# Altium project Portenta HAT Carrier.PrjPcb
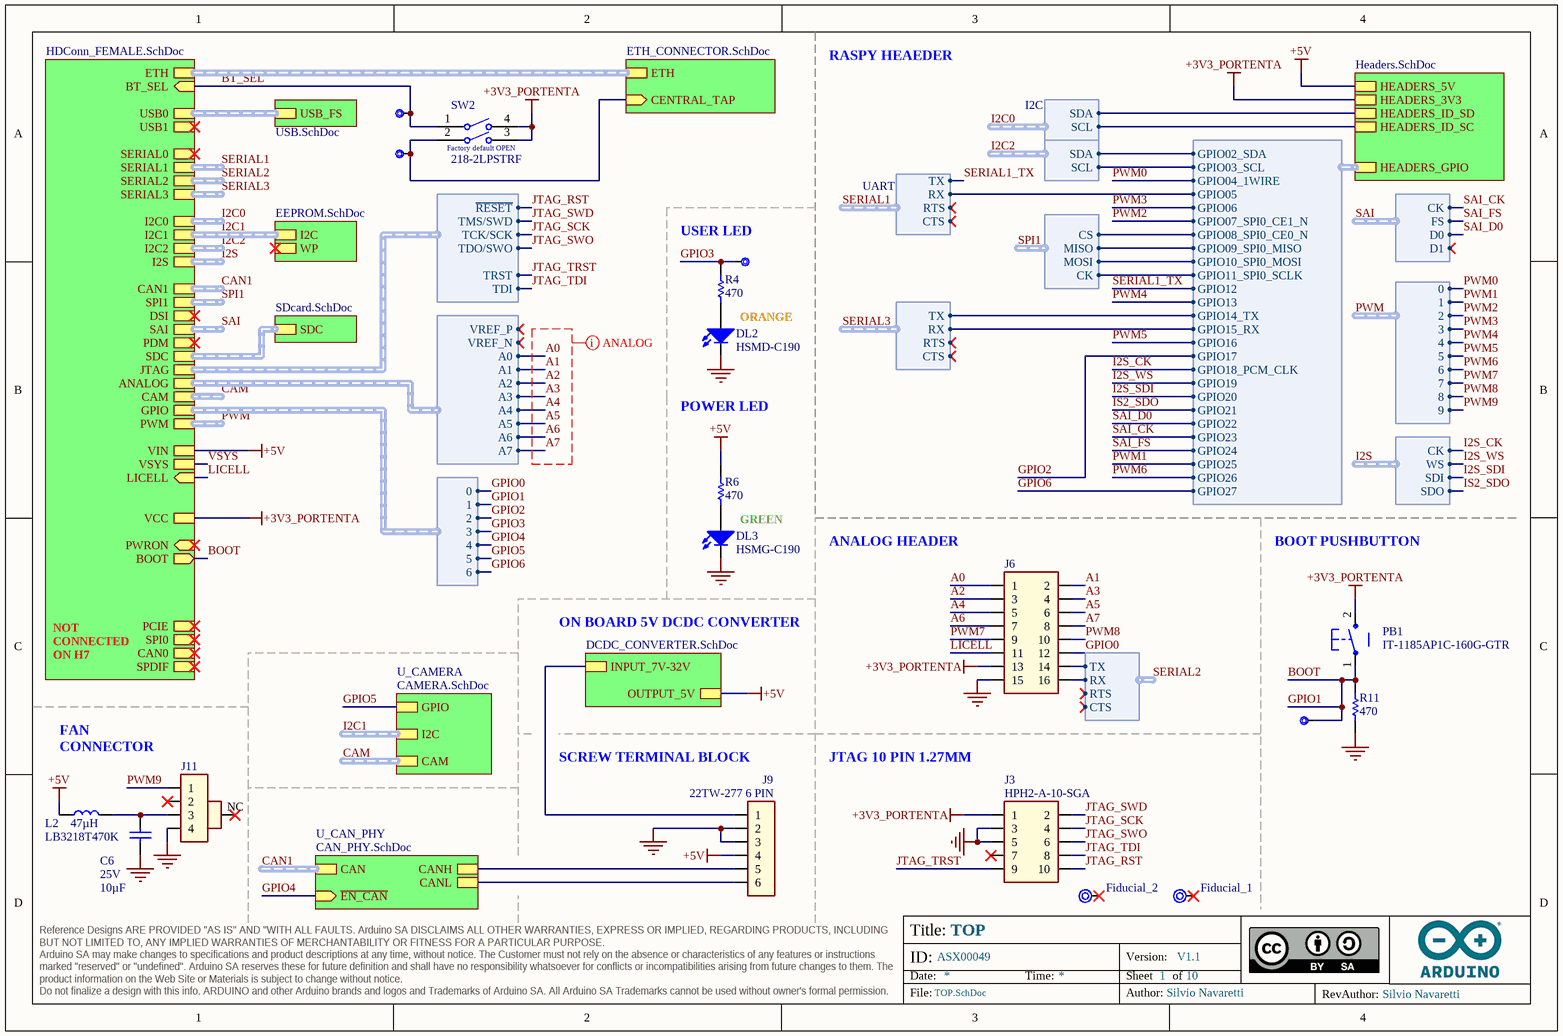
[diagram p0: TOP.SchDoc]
ASSEMBLY_BGA: _; ASSEMBLY_PRESSFIT: _; ASSEMBLY_SMD: X; ASSEMBLY_THT: X; BOARD_CODENAME: PORTENTA HAT CARRIER; BOARD_INFO_AUTHOR: Silvio Navaretti; BOARD_INFO_AUTHOR_REV: Silvio Navaretti; BOARD_INFO_Er: _; BOARD_INFO_FLEX: _; BOARD_INFO_FR4: X; BOARD_INFO_FR4_HTG: _; BOARD_INFO_IPC1: _; BOARD_INFO_IPC2: X; BOARD_INFO_IPC3: _; BOARD_INFO_IPC_NA: _; BOARD_INFO_NUMBER_OF_LAYERS: 4; BOARD_INFO_PCB_SIZE: 85mm x 56mm; BOARD_INFO_POLYMIDE: _; BOARD_INFO_RIGID: X; BOARD_INFO_RIGID/FLEX: _; BOARD_INFO_TBD: _; BOARD_INFO_THICKNESS: 1.6mm; DRILLS_BLIND: _; DRILLS_BURIED: _; DRILLS_COPPER_FILLING: _; DRILLS_FULL: X; DRILLS_LASER: _; DRILLS_PRESSFIT: _; DRILLS_RESIN_FILLING: _; DRILLS_SLOT: _; DRILLS_SOLDER_FILLING: X; FINISH_ADJUSTMENTS: _; FINISH_EDGE_PLATING: _; FINISH_ENIG: X; FINISH_HAL: _; FINISH_HAL_LF: _; FINISH_NI/AU: _; FINISH_SILK_BOTTOM: X; FINISH_SILK_COLOR: WHITE; FINISH_SILK_TOP: X; FINISH_SN/PB: _; FINISH_SOLDERMASK_BOTTOM: X; FINISH_SOLDERMASK_COLOR: BLACK; FINISH_SOLDERMASK_PEELABLE_BOTTOM: _; FINISH_SOLDERMASK_PEELABLE_COLOR: _; FINISH_SOLDERMASK_PEELABLE_TOP: _; FINISH_SOLDERMASK_TOP: X; FINISH_TABS: _; FINISH_TBD: _; INSULATION_MIN_INNER: 0.127mm; INSULATION_MIN_OUTER: 0.127mm; PANEL_MILLING: X; PANEL_NOT_REQUESTED: _; PANEL_NUMBER_OF_FIGURES: 6; PANEL_PROVIDED: X; PANEL_REQUESTED: _; PANEL_SCORING: X; PANEL_SIZE: 203mm x 188mm; PANEL_TABS: _; SKU: ASX00049; TRACK_MIN_WIDTH_INNER: 0.15mm; TRACK_MIN_WIDTH_OUTER: 0.15mm; VERSION: V1.1; VIA_1: _; VIA_1_HOLE_MM: _; VIA_1_PAD_MM: _; VIA_2: _; VIA_2_HOLE_MM: _; VIA_2_PAD_MM: _; VIA_3: _; VIA_3_HOLE_MM: _; VIA_3_PAD_MM: _; VIA_4: _; VIA_4_HOLE_MM: _; VIA_4_PAD_MM: _; VIA_5: _; VIA_5_HOLE_MM: _; VIA_5_PAD_MM: _; VIA_THROUGH: X; VIA_THROUGH_HOLE_MM: 0.3; VIA_THROUGH_PAD_MM: 0.6
10 sheets, 75 parts. Net scope: hierarchical (ports join the sheet entries above them; power ports are global).
Board files: PCB.PcbDoc, PANEL.PcbDoc
Sheets:
  TOP.SchDoc
    HDConnectors FEMALE = HDConn_FEMALE.SchDoc
    U_Headers = Headers.SchDoc
    MICRO USB CONNECTOR = USB.SchDoc
    U_SDcard = SDcard.SchDoc
    U_ETH_CONNECTOR = ETH_CONNECTOR.SchDoc
    DCDC_CONVERTER = DCDC_CONVERTER.SchDoc
    U_CAMERA = CAMERA.SchDoc
    U_CAN_PHY = CAN_PHY.SchDoc
    U_EEPROM = EEPROM.SchDoc

## Sheet TOP.SchDoc: TOP
size A4; Author: Silvio Navaretti; CompanyName: Arduino srl; DocumentNumber: ASX00049; Revision: V1.1; SheetNumber: 1; SheetTotal: 10; RevAuthor: Silvio Navaretti

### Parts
BOOT_PUSHBUTTON  CMP-018-0005-A.3  [TP-1.00MM]  (value not drawn)  (no BOM)
BT_SEL  CMP-018-0005-A.3  [TP-1.00MM]  (value not drawn)  (no BOM)
C6  value 10µF  Voltage: 25V  [CAP-0603]  (hidden comment: C1608A106M250NT)
CENTER_TAP  CMP-018-0005-A.3  [TP-1.00MM]  (value not drawn)  (no BOM)
DL2  HSMD-C190  [LEDC1608X80N-AK]
DL3  HSMG-C190  [LEDC1608X80N-AK]
Fiducial_1  Fiducial mark 1mm with 2mm solder  [Fiducial mark 1mm with circle-Footprint-1]  (value not drawn)  (no BOM)
Fiducial_2  Fiducial mark 1mm with 2mm solder  [Fiducial mark 1mm with circle-Footprint-1]  (value not drawn)  (no BOM)
J3  HPH2-A-10-SGA  [PINHEAD_2X05_127]
J6  PH2-16-UA  [PIN HEADER 2.54mm VERT. 2x8POS]  (value not drawn)
J9  22TW-277 6 PIN  [22TW-277 6 PIN]
J11  47053-1000  [47053-1000-Footprint-1]  (value not drawn)
L2  LB3218T470K  Inductance: 47µH  [INDC3218X20N]
LED_USER  CMP-018-0005-A.3  [TP-1.00MM]  (value not drawn)  (no BOM)
PB1  IT-1185AP1C-160G-GTR  [C&K_PTS820_NO_HOLES-1]
R4  value 470  [RES-0603]  (hidden comment: CRCW0603470RFKEAC)
R6  value 470  [RES-0603]  (hidden comment: CRCW0603470RFKEAC)
R11  value 470  [RES-0603]  (hidden comment: CRCW0603470RFKEAC)
SW2  218-2LPSTRF  [CTS-218-2LPST_V]

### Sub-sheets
DCDC_CONVERTER = DCDC_CONVERTER.SchDoc: INPUT_7V-32V, OUTPUT_5V
HDConnectors FEMALE = HDConn_FEMALE.SchDoc: PWRON (in), BOOT (out), USB1 (harness USB), SERIAL0 (harness UART), SAI (harness SAI), I2C2 (harness I2C), USB0 (harness USB), JTAG (harness JTAG), BT_SEL (in), I2S (harness I2S), I2C0 (harness I2C), ETH (harness ETH), PWM (harness GPIO), I2C1 (harness I2C), GPIO (harness GPIO), SPI1 (harness SPI), VCC, SERIAL3 (harness UART), CAM (harness CAMERA), LICELL (in), PDM (harness PDM), DSI (harness DISPLAY), CAN1 (harness CAN), SDC (harness SDC), SERIAL2 (harness UART), ANALOG (harness ANALOG), SERIAL1 (harness UART), VIN, VSYS, CAN0 (harness GPIO), SPI0 (harness GPIO), PCIE (harness GPIO), SPDIF (harness GPIO)
MICRO USB CONNECTOR = USB.SchDoc: USB_FS (harness USB)
U_CAMERA = CAMERA.SchDoc: I2C (harness I2C), CAM (harness CAMERA), GPIO
U_CAN_PHY = CAN_PHY.SchDoc: CAN (harness CAN), ~{EN_CAN} (in), CANH, CANL
U_EEPROM = EEPROM.SchDoc: I2C (harness I2C), WP
U_ETH_CONNECTOR = ETH_CONNECTOR.SchDoc: ETH (harness ETH), CENTRAL_TAP (in)
U_Headers = Headers.SchDoc: HEADERS_ID_SD, HEADERS_ID_SC, HEADERS_GPIO (harness HEADERS_GPIO), HEADERS_3V3, HEADERS_5V
U_SDcard = SDcard.SchDoc: SDC (harness SDC)

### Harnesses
HEADERS_GPIO: GPIO02_SDA, GPIO03_SCL, GPIO04_1WIRE, GPIO05, GPIO06, GPIO07_SPI0_CE1_N, GPIO08_SPI0_CE0_N, GPIO09_SPI0_MISO, GPIO10_SPI0_MOSI, GPIO11_SPI0_SCLK, GPIO12, GPIO13, GPIO14_TX, GPIO15_RX, GPIO16, GPIO17, GPIO18_PCM_CLK, GPIO19, GPIO20, GPIO21, GPIO22, GPIO23, GPIO24, GPIO25, GPIO26, GPIO27
UART: RX, TX, RTS, CTS
I2S: CK, SDI, SDO, WS
SPI: CS, CK, MISO, MOSI
I2C: SCL, SDA
I2C: SDA, SCL
SAI: CK, FS, D0, D1
JTAG: ~{RESET}, TCK/SCK, TDI, TDO/SWO, TMS/SWD, TRST
GPIO: 0, 1, 2, 3, 4, 5, 6
ANALOG: VREF_P, A0, A1, A2, A3, A7, A6, A5, A4, VREF_N
PWM: 0, 1, 2, 3, 4, 5, 6, 7, 8, 9

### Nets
+3V3_PORTENTA: J3.1 J6.13 PB1.2 SW2.3 SW2.4 ; sheet HDConnectors FEMALE/VCC, sheet U_Headers/HEADERS_3V3
+5V: J9.4 L2.1 R6.2 ; sheet HDConnectors FEMALE/VIN, sheet U_Headers/HEADERS_5V, sheet DCDC_CONVERTER/OUTPUT_5V
GND: C6.1 DL2.C DL3.C J3.3 J3.5 J6.15 J9.2 J9.3 J11.4 R11.1
A0: J6.1 ; sheet HDConnectors FEMALE/ANALOG.A0
A1: J6.2 ; sheet HDConnectors FEMALE/ANALOG.A1
A2: J6.3 ; sheet HDConnectors FEMALE/ANALOG.A2
A3: J6.4 ; sheet HDConnectors FEMALE/ANALOG.A3
A4: J6.5 ; sheet HDConnectors FEMALE/ANALOG.A4
A5: J6.6 ; sheet HDConnectors FEMALE/ANALOG.A5
A6: J6.7 ; sheet HDConnectors FEMALE/ANALOG.A6
A7: J6.8 ; sheet HDConnectors FEMALE/ANALOG.A7
BOOT: BOOT_PUSHBUTTON.X PB1.1 R11.2 ; sheet HDConnectors FEMALE/BOOT, sheet HDConnectors FEMALE/GPIO.1  [also labelled GPIO1]
BT_SEL: BT_SEL.X SW2.1 ; sheet HDConnectors FEMALE/BT_SEL
GPIO0: J6.12 ; sheet HDConnectors FEMALE/GPIO.0
GPIO2: sheet U_Headers/HEADERS_GPIO.GPIO17, sheet HDConnectors FEMALE/GPIO.2  [project net GPIO17]
GPIO02_SDA: sheet U_Headers/HEADERS_GPIO.GPIO02_SDA, sheet HDConnectors FEMALE/I2C2.SDA
GPIO3: LED_USER.X R4.2 ; sheet HDConnectors FEMALE/GPIO.3
GPIO03_SCL: sheet U_Headers/HEADERS_GPIO.GPIO03_SCL, sheet HDConnectors FEMALE/I2C2.SCL
GPIO4: sheet U_CAN_PHY/~{EN_CAN}, sheet HDConnectors FEMALE/GPIO.4
GPIO05: sheet U_Headers/HEADERS_GPIO.GPIO05, sheet HDConnectors FEMALE/SERIAL1.RX
GPIO5: sheet U_CAMERA/GPIO, sheet HDConnectors FEMALE/GPIO.5
GPIO6: sheet U_Headers/HEADERS_GPIO.GPIO27, sheet HDConnectors FEMALE/GPIO.6  [project net GPIO27]
GPIO08_SPI0_CE0_N: sheet U_Headers/HEADERS_GPIO.GPIO08_SPI0_CE0_N, sheet HDConnectors FEMALE/SPI1.CS
GPIO09_SPI0_MISO: sheet U_Headers/HEADERS_GPIO.GPIO09_SPI0_MISO, sheet HDConnectors FEMALE/SPI1.MISO
GPIO10_SPI0_MOSI: sheet U_Headers/HEADERS_GPIO.GPIO10_SPI0_MOSI, sheet HDConnectors FEMALE/SPI1.MOSI
GPIO11_SPI0_SCLK: sheet U_Headers/HEADERS_GPIO.GPIO11_SPI0_SCLK, sheet HDConnectors FEMALE/SPI1.CK
GPIO14_TX: sheet U_Headers/HEADERS_GPIO.GPIO14_TX, sheet HDConnectors FEMALE/SERIAL3.TX
GPIO15_RX: sheet U_Headers/HEADERS_GPIO.GPIO15_RX, sheet HDConnectors FEMALE/SERIAL3.RX
I2C0.SCL: sheet U_Headers/HEADERS_ID_SC, sheet HDConnectors FEMALE/I2C0.SCL
I2C0.SDA: sheet U_Headers/HEADERS_ID_SD, sheet HDConnectors FEMALE/I2C0.SDA
I2S_CK: sheet U_Headers/HEADERS_GPIO.GPIO18_PCM_CLK, sheet HDConnectors FEMALE/I2S.CK  [project net GPIO18_PCM_CLK]
I2S_SDI: sheet U_Headers/HEADERS_GPIO.GPIO20, sheet HDConnectors FEMALE/I2S.SDI  [project net GPIO20]
I2S_WS: sheet U_Headers/HEADERS_GPIO.GPIO19, sheet HDConnectors FEMALE/I2S.WS  [project net GPIO19]
IS2_SDO: sheet U_Headers/HEADERS_GPIO.GPIO21, sheet HDConnectors FEMALE/I2S.SDO  [project net GPIO21]
JTAG_RST: J3.10 ; sheet HDConnectors FEMALE/JTAG.~{RESET}
JTAG_SCK: J3.4 ; sheet HDConnectors FEMALE/JTAG.TCK/SCK
JTAG_SWD: J3.2 ; sheet HDConnectors FEMALE/JTAG.TMS/SWD
JTAG_SWO: J3.6 ; sheet HDConnectors FEMALE/JTAG.TDO/SWO
JTAG_TDI: J3.8 ; sheet HDConnectors FEMALE/JTAG.TDI
JTAG_TRST: J3.9 ; sheet HDConnectors FEMALE/JTAG.TRST
LICELL: J6.11 ; sheet HDConnectors FEMALE/LICELL
PWM0: sheet U_Headers/HEADERS_GPIO.GPIO04_1WIRE, sheet HDConnectors FEMALE/PWM.0  [project net GPIO04_1WIRE]
PWM1: sheet U_Headers/HEADERS_GPIO.GPIO25, sheet HDConnectors FEMALE/PWM.1  [project net GPIO25]
PWM2: sheet U_Headers/HEADERS_GPIO.GPIO07_SPI0_CE1_N, sheet HDConnectors FEMALE/PWM.2  [project net GPIO07_SPI0_CE1_N]
PWM3: sheet U_Headers/HEADERS_GPIO.GPIO06, sheet HDConnectors FEMALE/PWM.3  [project net GPIO06]
PWM4: sheet U_Headers/HEADERS_GPIO.GPIO13, sheet HDConnectors FEMALE/PWM.4  [project net GPIO13]
PWM5: sheet U_Headers/HEADERS_GPIO.GPIO16, sheet HDConnectors FEMALE/PWM.5  [project net GPIO16]
PWM6: sheet U_Headers/HEADERS_GPIO.GPIO26, sheet HDConnectors FEMALE/PWM.6  [project net GPIO26]
PWM7: J6.9 ; sheet HDConnectors FEMALE/PWM.7  [project net PWM.7]
PWM8: J6.10 ; sheet HDConnectors FEMALE/PWM.8  [project net PWM.8]
PWM9: J11.1 ; sheet HDConnectors FEMALE/PWM.9  [project net PWM.9]
SAI_CK: sheet U_Headers/HEADERS_GPIO.GPIO23, sheet HDConnectors FEMALE/SAI.CK  [project net GPIO23]
SAI_D0: sheet U_Headers/HEADERS_GPIO.GPIO22, sheet HDConnectors FEMALE/SAI.D0  [project net GPIO22]
SAI_FS: sheet U_Headers/HEADERS_GPIO.GPIO24, sheet HDConnectors FEMALE/SAI.FS  [project net GPIO24]
SERIAL1_TX: sheet U_Headers/HEADERS_GPIO.GPIO12, sheet HDConnectors FEMALE/SERIAL1.TX  [project net GPIO12]
SERIAL2.RX: J6.16 ; sheet HDConnectors FEMALE/SERIAL2.RX
SERIAL2.TX: J6.14 ; sheet HDConnectors FEMALE/SERIAL2.TX
NetC6_2: C6.2 J11.3 L2.2
NetCENTER_TAP_X: CENTER_TAP.X SW2.2 ; sheet U_ETH_CONNECTOR/CENTRAL_TAP
NetD2_A: J9.1 ; sheet DCDC_CONVERTER/INPUT_7V-32V
NetDL2_A: DL2.A R4.1
NetDL3_A: DL3.A R6.1
NetJ9_5: J9.5 ; sheet U_CAN_PHY/CANH
NetJ9_6: J9.6 ; sheet U_CAN_PHY/CANL

Not connected (* = marked no-connect by the designer): Fiducial_1 1*; Fiducial_2 1*; J3 7*; J11 2* NC*

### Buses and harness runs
harness CAM = sheet HDConnectors FEMALE/CAM
harness CAM = sheet U_CAMERA/CAM
harness CAN1 = sheet HDConnectors FEMALE/CAN1
harness CAN1 = sheet U_CAN_PHY/CAN
harness I2C0 = sheet HDConnectors FEMALE/I2C0
harness I2C1 = sheet HDConnectors FEMALE/I2C1 = sheet U_EEPROM/I2C
harness I2C1 = sheet U_CAMERA/I2C
harness I2C2 = sheet HDConnectors FEMALE/I2C2
harness I2S = sheet HDConnectors FEMALE/I2S
harness PWM = sheet HDConnectors FEMALE/PWM
harness SAI = sheet HDConnectors FEMALE/SAI
harness SERIAL1 = sheet HDConnectors FEMALE/SERIAL1
harness SERIAL2 = sheet HDConnectors FEMALE/SERIAL2
harness SERIAL3 = sheet HDConnectors FEMALE/SERIAL3
harness sheet HDConnectors FEMALE/ETH = sheet U_ETH_CONNECTOR/ETH
harness sheet HDConnectors FEMALE/SDC = sheet U_SDcard/SDC
harness sheet HDConnectors FEMALE/USB0 = sheet MICRO USB CONNECTOR/USB_FS
harness SPI1 = sheet HDConnectors FEMALE/SPI1

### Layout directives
net class ANALOG: A0, A1, A2, A3, A4, A5, A6, A7

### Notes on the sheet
- RASPY HEAEDER
- (near LED_USER) USER LED
- ORANGE
- POWER LED
- GREEN
- (near J6) ANALOG HEADER
- BOOT PUSHBUTTON
- NOT CONNECTED
  ON H7
- ON BOARD 5V DCDC CONVERTER
- CAMERA
- (near J11) FAN CONNECTOR
- (near J9) SCREW TERMINAL BLOCK
- (near J3) JTAG 10 PIN 1.27MM
- (near J11) CAN PHY SHARED WITH RASPY HEADERS

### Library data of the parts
BOOT_PUSHBUTTON BT_SEL CENTER_TAP LED_USER = UT0013-A.4: Test point 1.00mm
C6 = C0047-A.18: CAP CHIP 0603 10uF 20% 25V X5R; Manufacturer: Hottech; Code Arduino: 2213
DL2 = L0007-A.8: LED SMD 0603 ORANGE604 8mcd DIFF.; Manufacturer: Broadcom; Code Arduino: 2207
DL3 = L0009-A.5: LED SMD 0603 GREEN/568 15mcd 120^; Manufacturer: Broadcom; Code Arduino: 2204
Fiducial_1 Fiducial_2 = UT0024-A.6
J3 = J0068-A.9: CONN CONN STRIP THD 1,27 M/2/D 10v AuF H6,3 JTAG; Manufacturer: Adam Tech; Code Arduino: 0171
J6 = J0327-A.2: HEADER TH 2.54mm VERT. MALE 2x8POS; Manufacturer: Adam Tech; Code Arduino: J0327
J9 = J0319-A.3: CONN SCREW TERMINAL 22TW-277 6 PIN; Manufacturer: 4U CON; Code Arduino: J0319; Number of Contacts: 6; Max Current Rating: 10A
J11 = J0335-A.3: CONN header 2.54mm TH Male 1x4 pitch with locking; Manufacturer: Molex; Connector Type: BOARD CONNECTOR; Number of Contacts: 4; Code Arduino: J0335
L2 = I0048-A.3: IND CHIP SMD 1207 47uH 10% 1 ELEMENT; Manufacturer: Taiyo Yuden; Test Frequency: 2.52MHz; Code Arduino: I0048; DC Resistance (DCR): 920mR
PB1 = B0001-A.7: PUSHBUTTON WHITE NO ANCHORS; Manufacturer: Switronic; Code Arduino: 0173
R4 R6 R11 = R0124-A.22: RES CHIP 0603 470R 1% 1/10W; Manufacturer: Vishay; Power: 100mW; Code Arduino: A5111; Temperature coefficient: 100ppm
SW2 = S0022-A.4: SWITCH DIP NORMALLY OPEN; Manufacturer: CTS Corporation; Code Arduino: S0022; Number of Positions: 2; Throw Configuration: SPST; Contact Resistance: 100mR; Current Rating: 25mA; Voltage Rating (DC): 24V; Washable: Yes; Pitch: 0.05inch; Electrical Life: 1000Cycles; Actuator Type: Slide (Standard)

## Sheet HDConn_FEMALE.SchDoc: HD Connectors female
size A3; Author: Silvio Navaretti; CompanyName: Arduino srl; DocumentNumber: ASX00049; Revision: V1.1; SheetNumber: 3; SheetTotal: 10; RevAuthor: Silvio Navaretti
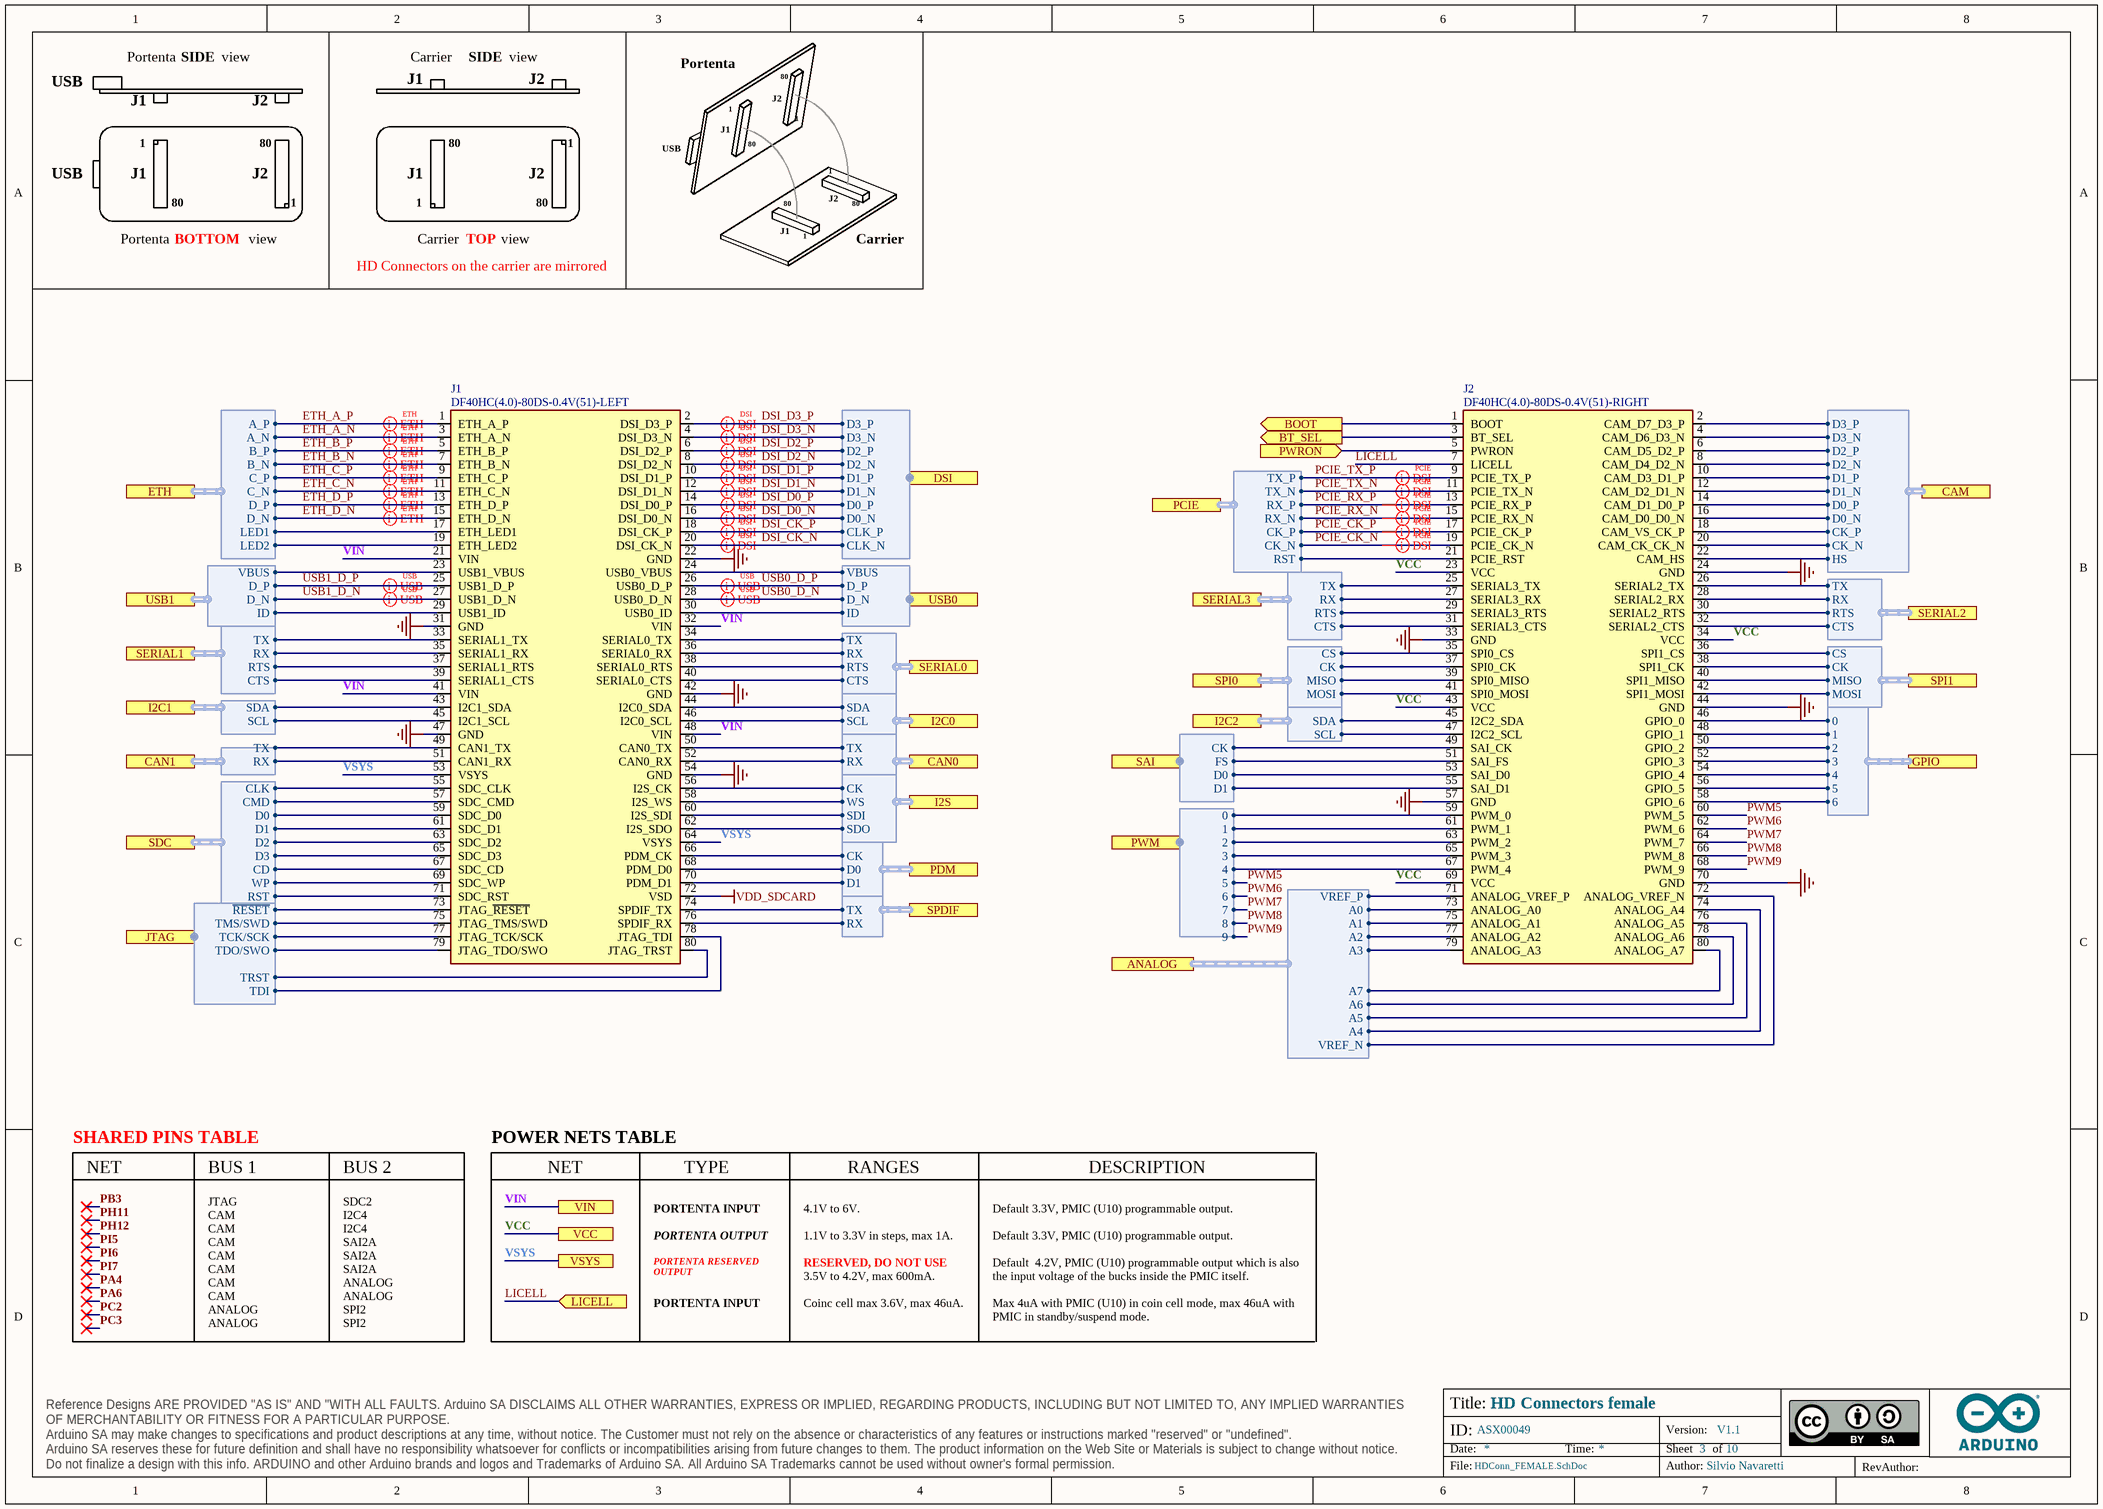
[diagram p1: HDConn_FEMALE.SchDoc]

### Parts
J1  DF40HC(4.0)-80DS-0.4V(51)-LEFT  [DF40HC(4.0)-80DS-0.4V(51)]
J2  DF40HC(4.0)-80DS-0.4V(51)-RIGHT  [DF40HC(4.0)-80DS-0.4V(51)]

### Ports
ANALOG (harness ANALOG), BOOT (out), BT_SEL (out), CAM (harness CAMERA), CAN0 (harness CAN), CAN1 (harness CAN), DSI (harness DISPLAY), ETH (harness ETH), GPIO (harness GPIO), I2C0 (harness I2C), I2C1 (harness I2C), I2C2 (harness I2C), I2S (harness I2S), JTAG (harness JTAG), LICELL (in), PCIE (harness PCIE), PDM (harness PDM), PWM (harness PWM), PWRON (in), SAI (harness SAI), SDC (harness SDC), SERIAL0 (harness UART), SERIAL1 (harness UART), SERIAL2 (harness UART), SERIAL3 (harness UART), SPDIF (harness SPDIF), SPI0 (harness SPI), SPI1 (harness SPI), USB0 (harness USB), USB1 (harness USB), VCC, VIN, VSYS

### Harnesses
USB: VBUS, D_P, D_N, ID
UART: RX, TX, RTS, CTS
I2C: SCL, SDA
CAN: RX, TX
SDC: CLK, CMD, D0, D1, D2, D3, CD, WP, RST
JTAG: ~{RESET}, TCK/SCK, TDI, TDO/SWO, TMS/SWD, TRST
DISPLAY: CLK_N, CLK_P, D0_N, D0_P, D1_N, D1_P, D2_N, D2_P, D3_N, D3_P
I2C: SDA, SCL
I2S: CK, SDI, SDO, WS
PDM: CK, D0, D1
ETH: A_N, A_P, B_N, B_P, C_N, C_P, D_N, D_P, LED1, LED2
SPDIF: TX, RX
ANALOG: VREF_P, A0, A1, A2, A3, A7, A6, A5, A4, VREF_N
PWM: 0, 1, 2, 3, 4, 5, 6, 7, 8, 9
SAI: CK, FS, D0, D1
CAMERA: D3_P, D3_N, D2_P, D2_N, D1_P, D1_N, D0_P, D0_N, CK_P, CK_N, HS
SPI: CS, CK, MISO, MOSI
GPIO: 0, 1, 2, 3, 4, 5, 6
PCIE: TX_P, TX_N, RX_P, RX_N, CK_P, CK_N, RST

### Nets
GND: J1.22(GND) J1.31(GND) J1.42(GND) J1.47(GND) J1.54(GND) J2.24(GND) J2.33(GND) J2.44(GND) J2.57(GND) J2.70(GND)
VCC: J2.23(VCC) J2.34(VCC) J2.43(VCC) J2.69(VCC) ; port VCC  [project net +3V3_PORTENTA]
VDD_SDCARD: J1.72(VSD)
VIN: J1.21(VIN) J1.24(USB0_VBUS) J1.32(VIN) J1.41(VIN) J1.48(VIN) ; port VIN, port USB0.VBUS  [project net +5V]
A0: J2.73(ANALOG_A0) ; port ANALOG.A0
A1: J2.75(ANALOG_A1) ; port ANALOG.A1
A2: J2.77(ANALOG_A2) ; port ANALOG.A2
A3: J2.79(ANALOG_A3) ; port ANALOG.A3
A4: J2.74(ANALOG_A4) ; port ANALOG.A4
A5: J2.76(ANALOG_A5) ; port ANALOG.A5
A6: J2.78(ANALOG_A6) ; port ANALOG.A6
A7: J2.80(ANALOG_A7) ; port ANALOG.A7
BOOT: J2.1(BOOT) J2.48(GPIO_1) ; port BOOT, port GPIO.1
BT_SEL: J2.3(BT_SEL) ; port BT_SEL
CAM.CK_N: J2.20(CAM_CK_CK_N) ; port CAM.CK_N
CAM.CK_P: J2.18(CAM_VS_CK_P) ; port CAM.CK_P
CAM.D0_N: J2.16(CAM_D0_D0_N) ; port CAM.D0_N
CAM.D0_P: J2.14(CAM_D1_D0_P) ; port CAM.D0_P
CAM.D1_N: J2.12(CAM_D2_D1_N) ; port CAM.D1_N
CAM.D1_P: J2.10(CAM_D3_D1_P) ; port CAM.D1_P
CAM.D2_N: J2.8(CAM_D4_D2_N) ; port CAM.D2_N
CAM.D2_P: J2.6(CAM_D5_D2_P) ; port CAM.D2_P
CAM.D3_N: J2.4(CAM_D6_D3_N) ; port CAM.D3_N
CAM.D3_P: J2.2(CAM_D7_D3_P) ; port CAM.D3_P
CAM.HS: J2.22(CAM_HS) ; port CAM.HS
CAN1.RX: J1.51(CAN1_RX) ; port CAN1.RX
CAN1.TX: J1.49(CAN1_TX) ; port CAN1.TX
CD: J1.67(SDC_CD) ; port SDC.CD
CLK: J1.55(SDC_CLK) ; port SDC.CLK
CMD: J1.57(SDC_CMD) ; port SDC.CMD
D0: J1.59(SDC_D0) ; port SDC.D0
D1: J1.61(SDC_D1) ; port SDC.D1
D2: J1.63(SDC_D2) ; port SDC.D2
D3: J1.65(SDC_D3) ; port SDC.D3
DSI_CK_N: J1.20(DSI_CK_N) ; port DSI.CLK_N
DSI_CK_P: J1.18(DSI_CK_P) ; port DSI.CLK_P
DSI_D0_N: J1.16(DSI_D0_N) ; port DSI.D0_N
DSI_D0_P: J1.14(DSI_D0_P) ; port DSI.D0_P
DSI_D1_N: J1.12(DSI_D1_N) ; port DSI.D1_N
DSI_D1_P: J1.10(DSI_D1_P) ; port DSI.D1_P
DSI_D2_N: J1.8(DSI_D2_N) ; port DSI.D2_N
DSI_D2_P: J1.6(DSI_D2_P) ; port DSI.D2_P
DSI_D3_N: J1.4(DSI_D3_N) ; port DSI.D3_N
DSI_D3_P: J1.2(DSI_D3_P) ; port DSI.D3_P
ETH_A_N: J1.3(ETH_A_N) ; port ETH.A_N
ETH_A_P: J1.1(ETH_A_P) ; port ETH.A_P
ETH_B_N: J1.7(ETH_B_N) ; port ETH.B_N
ETH_B_P: J1.5(ETH_B_P) ; port ETH.B_P
ETH_C_N: J1.11(ETH_C_N) ; port ETH.C_N
ETH_C_P: J1.9(ETH_C_P) ; port ETH.C_P
ETH_D_N: J1.15(ETH_D_N) ; port ETH.D_N
ETH_D_P: J1.13(ETH_D_P) ; port ETH.D_P
ETH_LED1: J1.17(ETH_LED1) ; port ETH.LED1
ETH_LED2: J1.19(ETH_LED2) ; port ETH.LED2
GPIO0: J2.46(GPIO_0) ; port GPIO.0
GPIO02_SDA: J2.45(I2C2_SDA) ; port I2C2.SDA
GPIO3: J2.52(GPIO_3) ; port GPIO.3
GPIO03_SCL: J2.47(I2C2_SCL) ; port I2C2.SCL
GPIO4: J2.54(GPIO_4) ; port GPIO.4
GPIO04_1WIRE: J2.59(PWM_0) ; port PWM.0
GPIO05: J1.35(SERIAL1_RX) ; port SERIAL1.RX
GPIO5: J2.56(GPIO_5) ; port GPIO.5
GPIO06: J2.65(PWM_3) ; port PWM.3
GPIO07_SPI0_CE1_N: J2.63(PWM_2) ; port PWM.2
GPIO08_SPI0_CE0_N: J2.36(SPI1_CS) ; port SPI1.CS
GPIO09_SPI0_MISO: J2.40(SPI1_MISO) ; port SPI1.MISO
GPIO10_SPI0_MOSI: J2.42(SPI1_MOSI) ; port SPI1.MOSI
GPIO11_SPI0_SCLK: J2.38(SPI1_CK) ; port SPI1.CK
GPIO12: J1.33(SERIAL1_TX) ; port SERIAL1.TX
GPIO13: J2.67(PWM_4) ; port PWM.4
GPIO14_TX: J2.25(SERIAL3_TX) ; port SERIAL3.TX
GPIO15_RX: J2.27(SERIAL3_RX) ; port SERIAL3.RX
GPIO17: J2.50(GPIO_2) ; port GPIO.2
GPIO18_PCM_CLK: J1.56(I2S_CK) ; port I2S.CK
GPIO19: J1.58(I2S_WS) ; port I2S.WS
GPIO20: J1.60(I2S_SDI) ; port I2S.SDI
GPIO21: J1.62(I2S_SDO) ; port I2S.SDO
GPIO22: J2.53(SAI_D0) ; port SAI.D0
GPIO23: J2.49(SAI_CK) ; port SAI.CK
GPIO24: J2.51(SAI_FS) ; port SAI.FS
GPIO25: J2.61(PWM_1) ; port PWM.1
GPIO27: J2.58(GPIO_6) ; port GPIO.6
I2C0.SCL: J1.46(I2C0_SCL) ; port I2C0.SCL
I2C0.SDA: J1.44(I2C0_SDA) ; port I2C0.SDA
I2C1.SCL: J1.45(I2C1_SCL) ; port I2C1.SCL
I2C1.SDA: J1.43(I2C1_SDA) ; port I2C1.SDA
JTAG_RST: J1.73(JTAG_~{RESET}) ; port JTAG.~{RESET}
JTAG_SCK: J1.77(JTAG_TCK/SCK) ; port JTAG.TCK/SCK
JTAG_SWD: J1.75(JTAG_TMS/SWD) ; port JTAG.TMS/SWD
JTAG_SWO: J1.79(JTAG_TDO/SWO) ; port JTAG.TDO/SWO
JTAG_TDI: J1.78(JTAG_TDI) ; port JTAG.TDI
JTAG_TRST: J1.80(JTAG_TRST) ; port JTAG.TRST
LICELL: J2.7(LICELL) ; port LICELL
PCIE_CK_N: J2.19(PCIE_CK_N) ; port PCIE.CK_N
PCIE_CK_P: J2.17(PCIE_CK_P) ; port PCIE.CK_P
PCIE_RX_N: J2.15(PCIE_RX_N) ; port PCIE.RX_N
PCIE_RX_P: J2.13(PCIE_RX_P) ; port PCIE.RX_P
PCIE_TX_N: J2.11(PCIE_TX_N) ; port PCIE.TX_N
PCIE_TX_P: J2.9(PCIE_TX_P) ; port PCIE.TX_P
PWM5: J2.60(PWM_5) ; port PWM.5  [project net GPIO16]
PWM6: J2.62(PWM_6) ; port PWM.6  [project net GPIO26]
PWM7: J2.64(PWM_7) ; port PWM.7  [project net PWM.7]
PWM8: J2.66(PWM_8) ; port PWM.8  [project net PWM.8]
PWM9: J2.68(PWM_9) ; port PWM.9  [project net PWM.9]
SAI.D1: J2.55(SAI_D1) ; port SAI.D1
SERIAL1.CTS: J1.39(SERIAL1_CTS) ; port SERIAL1.CTS
SERIAL1.RTS: J1.37(SERIAL1_RTS) ; port SERIAL1.RTS
SERIAL2.CTS: J2.32(SERIAL2_CTS) ; port SERIAL2.CTS
SERIAL2.RTS: J2.30(SERIAL2_RTS) ; port SERIAL2.RTS
SERIAL2.RX: J2.28(SERIAL2_RX) ; port SERIAL2.RX
SERIAL2.TX: J2.26(SERIAL2_TX) ; port SERIAL2.TX
SERIAL3.CTS: J2.31(SERIAL3_CTS) ; port SERIAL3.CTS
SERIAL3.RTS: J2.29(SERIAL3_RTS) ; port SERIAL3.RTS
USB0_D_N: J1.28(USB0_D_N) ; port USB0.D_N
USB0_D_P: J1.26(USB0_D_P) ; port USB0.D_P
USB1_D_N: J1.27(USB1_D_N) ; port USB1.D_N
USB1_D_P: J1.25(USB1_D_P) ; port USB1.D_P
VSYS: J1.53(VSYS) J1.64(VSYS) ; port VSYS
NetJ1_23: J1.23(USB1_VBUS) ; port USB1.VBUS
NetJ1_29: J1.29(USB1_ID) ; port USB1.ID
NetJ1_30: J1.30(USB0_ID) ; port USB0.ID
NetJ1_34: J1.34(SERIAL0_TX) ; port SERIAL0.TX
NetJ1_36: J1.36(SERIAL0_RX) ; port SERIAL0.RX
NetJ1_38: J1.38(SERIAL0_RTS) ; port SERIAL0.RTS
NetJ1_40: J1.40(SERIAL0_CTS) ; port SERIAL0.CTS
NetJ1_50: J1.50(CAN0_TX) ; port CAN0.TX
NetJ1_52: J1.52(CAN0_RX) ; port CAN0.RX
NetJ1_66: J1.66(PDM_CK) ; port PDM.CK
NetJ1_68: J1.68(PDM_D0) ; port PDM.D0
NetJ1_69: J1.69(SDC_WP) ; port SDC.WP
NetJ1_70: J1.70(PDM_D1) ; port PDM.D1
NetJ1_71: J1.71(SDC_RST) ; port SDC.RST
NetJ1_74: J1.74(SPDIF_TX) ; port SPDIF.TX
NetJ1_76: J1.76(SPDIF_RX) ; port SPDIF.RX
NetJ2_5: J2.5(PWRON) ; port PWRON
NetJ2_21: J2.21(PCIE_RST) ; port PCIE.RST
NetJ2_35: J2.35(SPI0_CS) ; port SPI0.CS
NetJ2_37: J2.37(SPI0_CK) ; port SPI0.CK
NetJ2_39: J2.39(SPI0_MISO) ; port SPI0.MISO
NetJ2_41: J2.41(SPI0_MOSI) ; port SPI0.MOSI
NetJ2_71: J2.71(ANALOG_VREF_P) ; port ANALOG.VREF_P
NetJ2_72: J2.72(ANALOG_VREF_N) ; port ANALOG.VREF_N

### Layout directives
differential pair; differential pair class USB: USB0_D_N, USB0_D_P, USB1_D_N, USB1_D_P
differential pair; differential pair class DSI: DSI_CK_N, DSI_CK_P, DSI_D0_N, DSI_D0_P, DSI_D1_N, DSI_D1_P, DSI_D2_N, DSI_D2_P, DSI_D3_N, DSI_D3_P
differential pair; differential pair class ETH: ETH_A_N, ETH_A_P, ETH_B_N, ETH_B_P, ETH_C_N, ETH_C_P, ETH_D_N, ETH_D_P
differential pair; differential pair class PCIE: PCIE_CK_N, PCIE_CK_P, PCIE_RX_N, PCIE_RX_P, PCIE_TX_N, PCIE_TX_P

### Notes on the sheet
- USB
- Portenta
- J1
- SIDE
- view
- J2
- Carrier
- 1
- 80
- BOTTOM
- TOP
- HD Connectors on the carrier are mirrored
- SHARED PINS TABLE
- NET
- BUS 1
- BUS 2
- POWER NETS TABLE
- TYPE
- RANGES
- DESCRIPTION
- JTAG
- CAM
- SDC2
- I2C4
- SAI2A
- PORTENTA INPUT
- PORTENTA OUTPUT
- 4.1V to 6V.
- 1.1V to 3.3V in steps, max 1A.
- RESERVED, DO NOT USE
- Default 3.3V, PMIC (U10) programmable output.
- ANALOG
- SPI2
- PORTENTA RESERVED OUTPUT
- Coinc cell max 3.6V, max 46uA.
- 3.5V to 4.2V, max 600mA.
- Default  4.2V, PMIC (U10) programmable output which is also the input voltage of the bucks inside the PMIC itself.
- Max 4uA with PMIC (U10) in coin cell mode, max 46uA with PMIC in standby/suspend mode.

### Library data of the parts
J1 = J0155-A.6: CONN RCPT FEMALE D80POS 0.4MM SMD GOLD; Manufacturer: Hirose; Number of Contacts: 80; Current Rating: 300mA; Voltage Rating: 30V; Stack Height: 3.5mm; Code Arduino: J0155; Gender: Receptacle; Mated Stacking Heights: 4mm; Pitch: 0.016inch
J2 = J0156-A.5: CONN RCPT FEMALE D80POS 0.4MM SMD GOLD; Manufacturer: Hirose; Number of Contacts: 80; Current Rating: 300mA; Voltage Rating: 30V; Stack Height: 4mm; Code Arduino: J0155; Gender: Receptacle; Mated Stacking Heights: 3.5mm; Pitch: 0.016inch

## Sheet Headers.SchDoc: RASP HEADERS
size A4; Author: Silvio Navaretti; CompanyName: Arduino srl; DocumentNumber: ASX00049; Revision: V1.1; SheetNumber: 2; SheetTotal: 10; RevAuthor: Silvio Navaretti
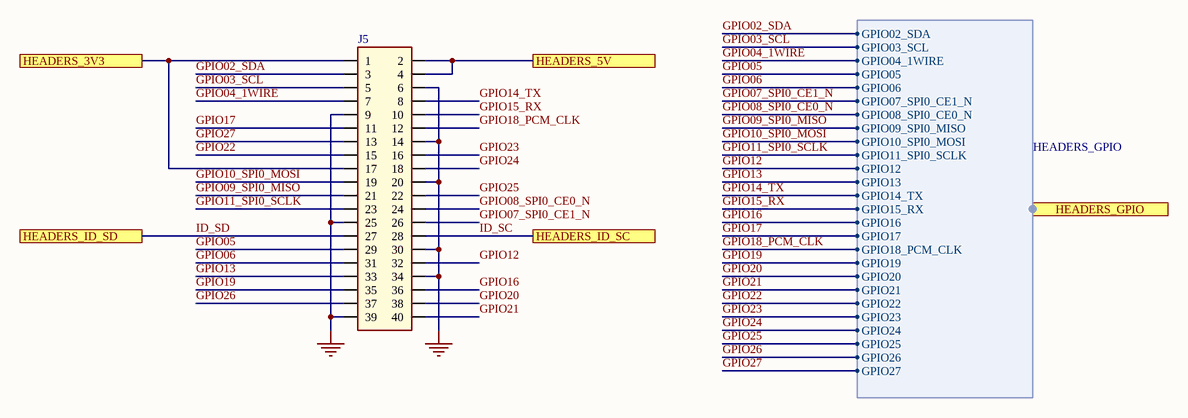
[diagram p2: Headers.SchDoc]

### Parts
J5  PH2-40-UA  [PIN HEADER 2.54mm VERT. 2x20POS]  (value not drawn)

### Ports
HEADERS_3V3, HEADERS_5V, HEADERS_GPIO (harness HEADERS_GPIO), HEADERS_ID_SC, HEADERS_ID_SD

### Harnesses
HEADERS_GPIO: GPIO02_SDA, GPIO03_SCL, GPIO04_1WIRE, GPIO05, GPIO06, GPIO07_SPI0_CE1_N, GPIO08_SPI0_CE0_N, GPIO09_SPI0_MISO, GPIO10_SPI0_MOSI, GPIO11_SPI0_SCLK, GPIO12, GPIO13, GPIO14_TX, GPIO15_RX, GPIO16, GPIO17, GPIO18_PCM_CLK, GPIO19, GPIO20, GPIO21, GPIO22, GPIO23, GPIO24, GPIO25, GPIO26, GPIO27

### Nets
+3V3_PORTENTA: J5.1 J5.17 ; port HEADERS_3V3
+5V: J5.2 J5.4 ; port HEADERS_5V
GND: J5.6 J5.9 J5.14 J5.20 J5.25 J5.30 J5.34 J5.39
GPIO02_SDA: J5.3 ; port HEADERS_GPIO.GPIO02_SDA
GPIO03_SCL: J5.5 ; port HEADERS_GPIO.GPIO03_SCL
GPIO04_1WIRE: J5.7 ; port HEADERS_GPIO.GPIO04_1WIRE
GPIO05: J5.29 ; port HEADERS_GPIO.GPIO05
GPIO06: J5.31 ; port HEADERS_GPIO.GPIO06
GPIO07_SPI0_CE1_N: J5.26 ; port HEADERS_GPIO.GPIO07_SPI0_CE1_N
GPIO08_SPI0_CE0_N: J5.24 ; port HEADERS_GPIO.GPIO08_SPI0_CE0_N
GPIO09_SPI0_MISO: J5.21 ; port HEADERS_GPIO.GPIO09_SPI0_MISO
GPIO10_SPI0_MOSI: J5.19 ; port HEADERS_GPIO.GPIO10_SPI0_MOSI
GPIO11_SPI0_SCLK: J5.23 ; port HEADERS_GPIO.GPIO11_SPI0_SCLK
GPIO12: J5.32 ; port HEADERS_GPIO.GPIO12
GPIO13: J5.33 ; port HEADERS_GPIO.GPIO13
GPIO14_TX: J5.8 ; port HEADERS_GPIO.GPIO14_TX
GPIO15_RX: J5.10 ; port HEADERS_GPIO.GPIO15_RX
GPIO16: J5.36 ; port HEADERS_GPIO.GPIO16
GPIO17: J5.11 ; port HEADERS_GPIO.GPIO17
GPIO18_PCM_CLK: J5.12 ; port HEADERS_GPIO.GPIO18_PCM_CLK
GPIO19: J5.35 ; port HEADERS_GPIO.GPIO19
GPIO20: J5.38 ; port HEADERS_GPIO.GPIO20
GPIO21: J5.40 ; port HEADERS_GPIO.GPIO21
GPIO22: J5.15 ; port HEADERS_GPIO.GPIO22
GPIO23: J5.16 ; port HEADERS_GPIO.GPIO23
GPIO24: J5.18 ; port HEADERS_GPIO.GPIO24
GPIO25: J5.22 ; port HEADERS_GPIO.GPIO25
GPIO26: J5.37 ; port HEADERS_GPIO.GPIO26
GPIO27: J5.13 ; port HEADERS_GPIO.GPIO27
ID_SC: J5.28 ; port HEADERS_ID_SC  [project net I2C0.SCL]
ID_SD: J5.27 ; port HEADERS_ID_SD  [project net I2C0.SDA]

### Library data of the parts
J5 = J0326-A.3: HEADER TH 2.54mm VERT. MALE 2x20POS; Manufacturer: Adam Tech; Code Arduino: J0326

## Sheet USB.SchDoc: USB
size A4; Author: Silvio Navaretti; CompanyName: Arduino srl; DocumentNumber: ASX00049; Revision: V1.1; SheetNumber: 6; SheetTotal: 10; RevAuthor: Silvio Navaretti
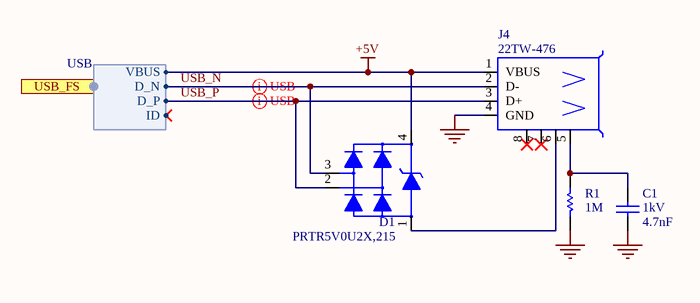
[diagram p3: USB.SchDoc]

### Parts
C1  value 4.7nF  Voltage: 1kV  [CAP-0805]  (hidden comment: FV21X472K102ECG)
D1  PRTR5V0U2X,215  [SOT190P230X110-4N]
J4  22TW-476  [22TW-476]
R1  value 1M  [RES-0603]  (hidden comment: CRCW06031M00FKEA)

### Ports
USB_FS (harness USB)

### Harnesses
USB: VBUS, D_P, D_N, ID

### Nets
+5V: D1.4 J4.1(VBUS) ; port USB_FS.VBUS
GND: C1.1 J4.4(GND) R1.1
USB_N: D1.3 J4.2(D-) ; port USB_FS.D_N  [project net USB0_D_N]
USB_P: D1.2 J4.3(D+) ; port USB_FS.D_P  [project net USB0_D_P]
NetC1_2: C1.2 J4.5(FX) R1.2
NetD1_1: D1.1 J4.6(FX)

Not connected (* = marked no-connect by the designer): J4 7(FX)* 8(FX)*

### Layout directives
differential pair; differential pair class USB: USB0_D_N, USB0_D_P

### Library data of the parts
C1 = C0059-A.14: CAP CHIP 0805 4.7nF 10% 1000V X7R; Manufacturer: PSA Shenzen; Code Arduino: 0689
D1 = D0025-A.5: TVS ARRAY 4LIN.8kV 1pF SOT143B; Manufacturer: Nexperia; Device Type: ESD protection; Code Arduino: 2209
J4 = J0334-A.4: CONN USB A 2.0 RECEPTACLE RIGHT ANGLE; Manufacturer: 4UCONN; Number of Contacts: 4; Code Arduino: J0334
R1 = R0163-A.20: RES CHIP 0603 1M 1% 1/10W; Manufacturer: Vishay; Power: 100mW; Code Arduino: R0163; Temperature coefficient: 100ppm

## Sheet SDcard.SchDoc: SD card
size A4; Author: Silvio Navaretti; CompanyName: Arduino srl; DocumentNumber: ASX00049; Revision: V1.1; SheetNumber: 7; SheetTotal: 10; RevAuthor: Silvio Navaretti
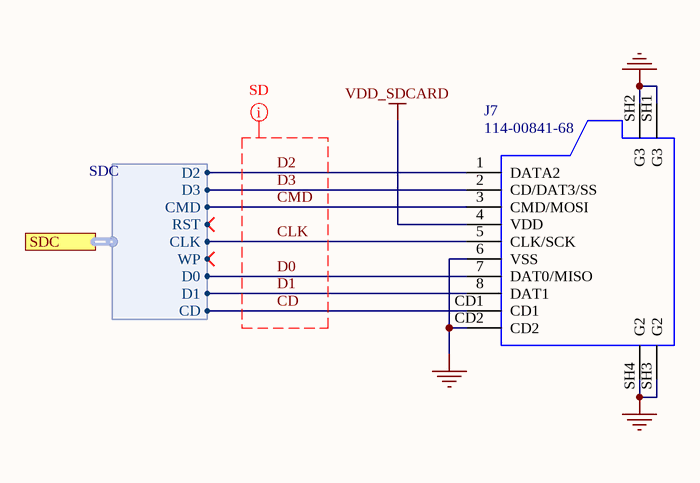
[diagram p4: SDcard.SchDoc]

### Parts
J7  114-00841-68  [AMPHENOL_114-00841-68]

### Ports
SDC (harness SDC)

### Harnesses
SDC: D0, D1, D2, D3, CMD, CLK, CD, WP, RST

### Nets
GND: J7.6(VSS) J7.CD2 J7.SH1(G3) J7.SH2(G3) J7.SH3(G2) J7.SH4(G2)
VDD_SDCARD: J7.4(VDD)
CD: J7.CD1 ; port SDC.CD
CLK: J7.5(CLK/SCK) ; port SDC.CLK
CMD: J7.3(CMD/MOSI) ; port SDC.CMD
D0: J7.7(DAT0/MISO) ; port SDC.D0
D1: J7.8(DAT1) ; port SDC.D1
D2: J7.1(DATA2) ; port SDC.D2
D3: J7.2(CD/DAT3/SS) ; port SDC.D3

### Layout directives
net class SD: CD, CLK, CMD, D0, D1, D2, D3

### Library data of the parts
J7 = J0011-A.5: CONN Micro SD; Manufacturer: Amphenol; Code Arduino: A5328

## Sheet ETH_CONNECTOR.SchDoc: ETHERNET
size A4; Author: Silvio Navaretti; CompanyName: Arduino srl; DocumentNumber: ASX00049; Revision: V1.1; SheetNumber: 5; SheetTotal: 10; RevAuthor: Silvio Navaretti
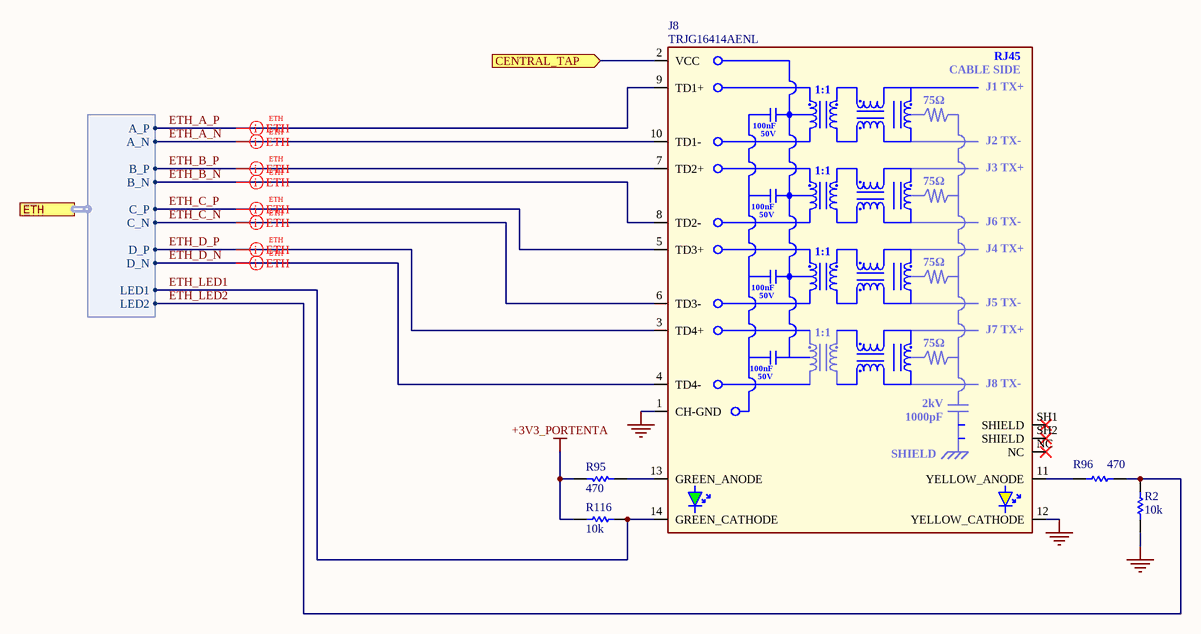
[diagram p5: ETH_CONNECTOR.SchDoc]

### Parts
J8  TRJG16414AENL  [TRJG16414AENL]
R2  value 10k  [RES-0603]  (hidden comment: CRCW060310K0JNEAC)
R95  value 470  [RES-0603]  (hidden comment: CRCW0603470RFKEAC)
R96  value 470  [RES-0603]  (hidden comment: CRCW0603470RFKEAC)
R116  value 10k  [RES-0603]  (hidden comment: CRCW060310K0JNEAC)

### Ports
CENTRAL_TAP (in), ETH (harness ETH)

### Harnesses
ETH: A_N, A_P, B_N, B_P, C_N, C_P, D_N, D_P, LED1, LED2

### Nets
+3V3_PORTENTA: R95.2 R116.2
GND: J8.1(CH-GND) J8.12(YELLOW_CATHODE) R2.2
ETH_A_N: J8.10(TD1-) ; port ETH.A_N
ETH_A_P: J8.9(TD1+) ; port ETH.A_P
ETH_B_N: J8.8(TD2-) ; port ETH.B_N
ETH_B_P: J8.7(TD2+) ; port ETH.B_P
ETH_C_N: J8.6(TD3-) ; port ETH.C_N
ETH_C_P: J8.5(TD3+) ; port ETH.C_P
ETH_D_N: J8.4(TD4-) ; port ETH.D_N
ETH_D_P: J8.3(TD4+) ; port ETH.D_P
ETH_LED1: J8.14(GREEN_CATHODE) R116.1 ; port ETH.LED1
ETH_LED2: R2.1 R96.2 ; port ETH.LED2
NetCENTER_TAP_X: J8.2(VCC) ; port CENTRAL_TAP
NetJ8_11: J8.11(YELLOW_ANODE) R96.1
NetJ8_13: J8.13(GREEN_ANODE) R95.1

Not connected (* = marked no-connect by the designer): J8 NC* SH1(SHIELD)* SH2(SHIELD)*

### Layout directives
differential pair; differential pair class ETH: ETH_A_N, ETH_A_P, ETH_B_N, ETH_B_P, ETH_C_N, ETH_C_P, ETH_D_N, ETH_D_P

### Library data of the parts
J8 = J0354-A.2: CONN ETH RJ45 TH 10/100/1000 integrated magnetics LED green LED yellow 21.25x15.95x13.45mm; Manufacturer: TRXCOM; Code Arduino: J0354
R2 R116 = R0090-A.22: RES CHIP 0603 10k 5% 1/10W B.5k; Manufacturer: Vishay; Code Arduino: 0028; Power: 100mW; Temperature coefficient: 200ppm
R95 R96 = R0124-A.22: as R4 on sheet TOP

## Sheet DCDC_CONVERTER.SchDoc: POWER EXTERNAL
size A4; Author: Silvio Navareetti; CompanyName: Arduino srl; DocumentNumber: ASX00049; Revision: V1.1; SheetNumber: 4; SheetTotal: 10; RevAuthor: Silvio Navaretti
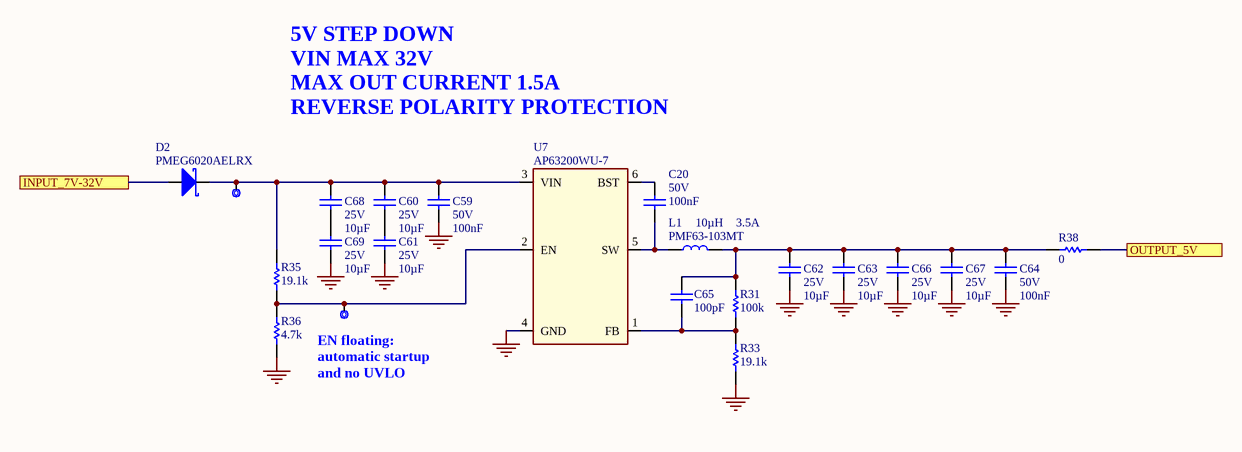
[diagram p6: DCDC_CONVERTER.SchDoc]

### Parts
C20  value 100nF  Voltage: 50V  [CAP-0603]  (hidden comment: 0603B104K500CT)
C59  value 100nF  Voltage: 50V  [CAP-0603]  (hidden comment: 0603B104K500CT)
C60  value 10µF  Voltage: 25V  [CAP-0603]  (hidden comment: C1608A106M250NT)
C61  value 10µF  Voltage: 25V  [CAP-0603]  (hidden comment: C1608A106M250NT)
C62  value 10µF  Voltage: 25V  [CAP-0603]  (hidden comment: C1608A106M250NT)
C63  value 10µF  Voltage: 25V  [CAP-0603]  (hidden comment: C1608A106M250NT)
C64  value 100nF  Voltage: 50V  [CAP-0603]  (hidden comment: 0603B104K500CT)
C65  value 100pF  [CAP-0603]  (hidden comment: C0603C101K2RAC7867)
C66  value 10µF  Voltage: 25V  [CAP-0603]  (hidden comment: C1608A106M250NT)
C67  value 10µF  Voltage: 25V  [CAP-0603]  (hidden comment: C1608A106M250NT)
C68  value 10µF  Voltage: 25V  [CAP-0603]  (hidden comment: C1608A106M250NT)
C69  value 10µF  Voltage: 25V  [CAP-0603]  (hidden comment: C1608A106M250NT)
D2  PMEG6020AELRX  [SOD123-1]
DCDC_EN  CMP-018-0005-A.3  [TP-1.00MM]  (value not drawn)  (no BOM)
DCDC_IN  CMP-018-0005-A.3  [TP-1.00MM]  (value not drawn)  (no BOM)
L1  PMF63-103MT  IRMS: 3.5A  Inductance: 10µH  [PMF63]
R31  value 100k  [RES-0603]  (hidden comment: CRCW0603100KFKEAC)
R33  value 19.1k  [RES-0603]  (hidden comment: CRCW060319K1FKEAC)
R35  value 19.1k  [RES-0603]  (hidden comment: CRCW060319K1FKEAC)
R36  value 4.7k  [RES-0603]  (hidden comment: AC0603FR-134K7L)
R38  value 0  [RES-0603]  (hidden comment: CRCW06030000Z0EAC)
U7  AP63200WU-7  [SOT95P280X100-6N]

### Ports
INPUT_7V-32V, OUTPUT_5V

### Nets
+5V: R38.2 ; port OUTPUT_5V
GND: C59.2 C61.1 C62.1 C63.1 C64.2 C66.1 C67.1 C69.1 R33.1 R36.2 U7.4(GND)
NetC20_1: C20.1 U7.6(BST)
NetC20_2: C20.2 L1.1 U7.5(SW)
NetC59_1: C59.1 C60.2 C68.2 D2.C DCDC_IN.X R35.1 U7.3(VIN)
NetC60_1: C60.1 C61.2
NetC62_2: C62.2 C63.2 C64.1 C65.2 C66.2 C67.2 L1.2 R31.1 R38.1
NetC65_1: C65.1 R31.2 R33.2 U7.1(FB)
NetC68_1: C68.1 C69.2
NetD2_A: D2.A ; port INPUT_7V-32V
NetDCDC_EN_X: DCDC_EN.X R35.2 R36.1 U7.2(EN)

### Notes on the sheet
- 5V STEP DOWN
  VIN MAX 32V
  MAX OUT CURRENT 1.5A
  REVERSE POLARITY PROTECTION
- (near DCDC_EN) EN floating: automatic startup and no UVLO

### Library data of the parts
C20 C59 C64 = C0043-A.14: CAP CHIP 0603 100nF 10% 50V X7R; Manufacturer: Walsin; Code Arduino: 0015
C60-C63 C66-C69 = C0047-A.18: as C6 on sheet TOP
C65 = C0081-A.12: CAP CHIP 0603 100pF 10% 200V X7R; Manufacturer: KEMET; Code Arduino: C0081
D2 = D0026-A.6: DIODE SCHOTTKY SMD 2A 60V SOD123FL; Manufacturer: Nexperia; Manucturer Part Number 2: SS26L; Code Arduino: 2208; Forward Voltage: 0.6V; Manucturer 2: Hottech
DCDC_EN DCDC_IN = UT0013-A.4: Test point 1.00mm
L1 = I0078-A.1: IND 10uH 20%, max 85mR, IRMS 3.5A, Isat 7A, 7.3x6.6x3mm; Manufacturer: K-WELL; DCR max: 85m; Code Arduino: I0078
R31 = R0116-A.22: RES CHIP 0603 100k 1% 1/10W; Manufacturer: Vishay; Power: 100mW; Code Arduino: 2022; Temperature coefficient: 100ppm
R33 = R0117-A.22: RES CHIP 0603 19k1 1% 1/10W; Manufacturer: Vishay; Code Arduino: 2461; Power: 100mW; Temperature coefficient: 100ppm
R35 = R0117-A.22: RES CHIP 0603 19k1 1% 1/10W; Manufacturer: Vishay; Power: 100mW; Code Arduino: 2461; Temperature coefficient: 100ppm
R36 = R0220-A.15: RES CHIP 0603 4k7 1% 1/10W; Manufacturer: Yageo; Power: 100mW; Code Arduino: R0220; Temperature coefficient: 100ppm
R38 = R0096-A.22: RES CHIP 0603 0R 1/10W; Manufacturer: Vishay; Power: 100mW; Tolerance: 0%; Code Arduino: 0233; Temperature coefficient: 0ppm
U7 = U0241-A.6: IC BUCK VIN 3V8 to 32V Iout 4A duty 100% fsw 500kHz TSOT26; Manufacturer: Diodes Incorporated; Code Arduino: U0241

## Sheet CAMERA.SchDoc: CAMERA
size A4; Author: Silvio Navaretti; CompanyName: Arduino srl; DocumentNumber: ASX00049; Revision: V1.1; SheetNumber: 9; SheetTotal: 10; RevAuthor: Silvio Navaretti
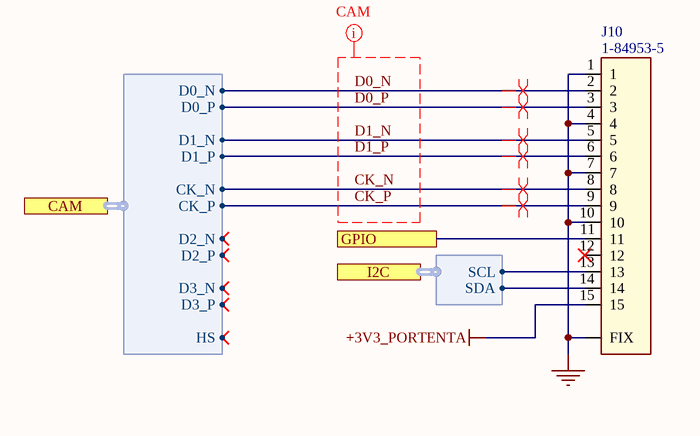
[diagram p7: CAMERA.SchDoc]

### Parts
J10  1-84953-5  [1-84952-5-Footprint-1]

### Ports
CAM (harness CAMERA), GPIO, I2C (harness I2C)

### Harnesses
I2C: SDA, SCL
CAMERA: D3_P, D3_N, D2_P, D2_N, D1_P, D1_N, D0_P, D0_N, CK_P, CK_N, HS

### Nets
+3V3_PORTENTA: J10.15
GND: J10.1 J10.4 J10.7 J10.10 J10.FIX
CK_N: J10.8 ; port CAM.CK_N  [project net CAM.CK_N]
CK_P: J10.9 ; port CAM.CK_P  [project net CAM.CK_P]
D0_N: J10.2 ; port CAM.D0_N  [project net CAM.D0_N]
D0_P: J10.3 ; port CAM.D0_P  [project net CAM.D0_P]
D1_N: J10.5 ; port CAM.D1_N  [project net CAM.D1_N]
D1_P: J10.6 ; port CAM.D1_P  [project net CAM.D1_P]
GPIO5: J10.11 ; port GPIO
I2C1.SCL: J10.13 ; port I2C.SCL
I2C1.SDA: J10.14 ; port I2C.SDA

Not connected (* = marked no-connect by the designer): J10 12*

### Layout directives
differential pair; differential pair class CAMERA: CAM.CK_N, CAM.CK_P, CAM.D0_N, CAM.D0_P, CAM.D1_N, CAM.D1_P
net class CAM: CK_N, CK_P, D0_N, D0_P, D1_N, D1_P

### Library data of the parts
J10 = J0320-A.3: CONN FFC/FPC Connector, 15 Contact(s), 1 Row(s), TOP CONTACT, Female, Right Angle, 1mm Pitch, Locking ZIF; Manufacturer: TE Connectivity; Number of Contacts: 15; Insulation Resistance: 1GR; Connector Type: CARD EDGE CONNECTOR; Contact Resistance: 10mR; Code Arduino: J0320

## Sheet CAN_PHY.SchDoc: CAN PHY
size A4; Author: Silvio Navaretti; CompanyName: Arduino srl; DocumentNumber: ASX00049; Revision: V1.1; SheetNumber: 8; SheetTotal: 10; RevAuthor: Silvio Navaretti
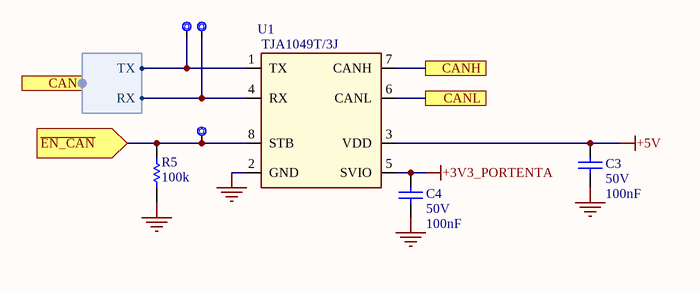
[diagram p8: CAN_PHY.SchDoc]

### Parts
C3  value 100nF  Voltage: 50V  [CAP-0603]  (hidden comment: 0603B104K500CT)
C4  value 100nF  Voltage: 50V  [CAP-0603]  (hidden comment: 0603B104K500CT)
CAN_EN  CMP-018-0005-A.3  [TP-1.00MM]  (value not drawn)  (no BOM)
CANRX  CMP-018-0005-A.3  [TP-1.00MM]  (value not drawn)  (no BOM)
CANTX  CMP-018-0005-A.3  [TP-1.00MM]  (value not drawn)  (no BOM)
R5  value 100k  [RES-0603]  (hidden comment: CRCW0603100KFKEAC)
U1  TJA1049T/3J  [TJA1049T_3J-Footprint-1]

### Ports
CAN (harness CAN), CANH, CANL, ~{EN_CAN} (in)

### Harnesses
CAN: RX, TX

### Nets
+3V3_PORTENTA: C4.1 U1.5(SVIO)
+5V: C3.1 U1.3(VDD)
GND: C3.2 C4.2 R5.1 U1.2(GND)
CAN1.RX: CANRX.X U1.4(RX) ; port CAN.RX
CAN1.TX: CANTX.X U1.1(TX) ; port CAN.TX
GPIO4: CAN_EN.X R5.2 U1.8(STB) ; port ~{EN_CAN}
NetJ9_5: U1.7(CANH) ; port CANH
NetJ9_6: U1.6(CANL) ; port CANL

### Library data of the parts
C3 C4 = C0043-A.14: as C20 on sheet DCDC_CONVERTER
CAN_EN CANRX CANTX = UT0013-A.4: Test point 1.00mm
R5 = R0116-A.22: as R31 on sheet DCDC_CONVERTER
U1 = U0114-A.7: IC CAN TRANSCEIVER 1Mbps STBY 5.25V SOIC8; Manufacturer: NXP; Code Arduino: U0114

## Sheet EEPROM.SchDoc: EEPROM
size A4; Author: Silvio Navaretti; CompanyName: Arduino srl; DocumentNumber: ASX00049; Revision: V1.1; SheetNumber: 10; SheetTotal: 10; RevAuthor: Silvio Navaretti
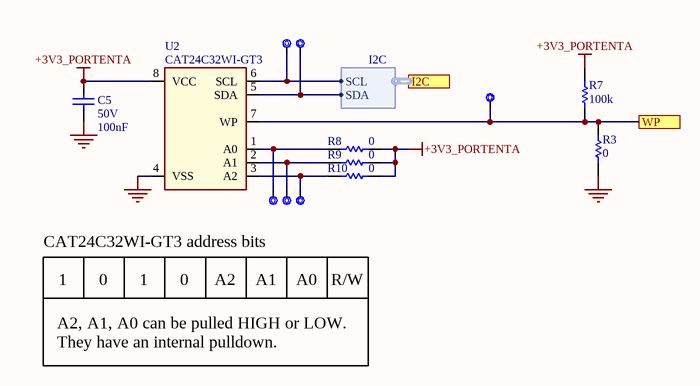
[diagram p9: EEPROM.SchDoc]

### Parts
C5  value 100nF  Voltage: 50V  [CAP-0603]  (hidden comment: 0603B104K500CT)
EEPROM_A0  CMP-018-0005-A.3  [TP-1.00MM]  (value not drawn)  (no BOM)
EEPROM_A1  CMP-018-0005-A.3  [TP-1.00MM]  (value not drawn)  (no BOM)
EEPROM_A2  CMP-018-0005-A.3  [TP-1.00MM]  (value not drawn)  (no BOM)
EEPROM_SCL  CMP-018-0005-A.3  [TP-1.00MM]  (value not drawn)  (no BOM)
EEPROM_SDA  CMP-018-0005-A.3  [TP-1.00MM]  (value not drawn)  (no BOM)
EEPROM_WP  CMP-018-0005-A.3  [TP-1.00MM]  (value not drawn)  (no BOM)
R3  value 0  [RES-0603]  (hidden comment: CRCW06030000Z0EAC)
R7  value 100k  [RES-0603]  (hidden comment: CRCW0603100KFKEAC)
R8  value 0  [RES-0603]  (hidden comment: CRCW06030000Z0EAC)
R9  value 0  [RES-0603]  (hidden comment: CRCW06030000Z0EAC)
R10  value 0  [RES-0603]  (hidden comment: CRCW06030000Z0EAC)
U2  CAT24C32WI-GT3  [SOIC8]

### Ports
I2C (harness I2C), WP

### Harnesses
I2C: SDA, SCL

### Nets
+3V3_PORTENTA: C5.1 R7.2 R8.2 R9.2 R10.2 U2.8(VCC)
GND: C5.2 R3.1 U2.4(VSS)
I2C1.SCL: EEPROM_SCL.X U2.6(SCL) ; port I2C.SCL
I2C1.SDA: EEPROM_SDA.X U2.5(SDA) ; port I2C.SDA
NetEEPROM_A0_X: EEPROM_A0.X R8.1 U2.1(A0)
NetEEPROM_A1_X: EEPROM_A1.X R9.1 U2.2(A1)
NetEEPROM_A2_X: EEPROM_A2.X R10.1 U2.3(A2)
NetEEPROM_WP_X: EEPROM_WP.X R3.2 R7.1 U2.7(WP) ; port WP

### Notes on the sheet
- 1
- CAT24C32WI-GT3 address bits
- 0
- A2
- A1
- A0
- R/W
- A2, A1, A0 can be pulled HIGH or LOW.
  They have an internal pulldown.

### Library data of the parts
C5 = C0043-A.14: as C20 on sheet DCDC_CONVERTER
EEPROM_A0-EEPROM_A2 EEPROM_SCL EEPROM_SDA EEPROM_WP = UT0013-A.4: Test point 1.00mm
R3 R8-R10 = R0096-A.22: RES CHIP 0603 0R 1/10W; Manufacturer: Vishay; Code Arduino: 0233; Power: 100mW; Tolerance: 0%; Temperature coefficient: 0ppm
R7 = R0116-A.22: RES CHIP 0603 100k 1% 1/10W; Manufacturer: Vishay; Code Arduino: 2022; Power: 100mW; Temperature coefficient: 100ppm
U2 = U0296-A.3: IC EEPROM, 32KX1, I2C, 1.7V TO 5.5V, SOIC8; Manufacturer: ON Semiconductor; Code Arduino: U0296

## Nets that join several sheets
+3V3_PORTENTA: TOP (5 pins), HDConn_FEMALE (J2.23 J2.34 J2.43 J2.69), Headers (J5.1 J5.17), ETH_CONNECTOR (R95.2 R116.2), CAMERA (J10.15), CAN_PHY (C4.1 U1.5), EEPROM (6 pins)
+5V: TOP (J9.4 L2.1 R6.2), HDConn_FEMALE (5 pins), Headers (J5.2 J5.4), USB (D1.4 J4.1), DCDC_CONVERTER (R38.2), CAN_PHY (C3.1 U1.3)
GND: TOP (10 pins), HDConn_FEMALE (10 pins), Headers (8 pins), USB (C1.1 J4.4 R1.1), SDcard (6 pins), ETH_CONNECTOR (J8.1 J8.12 R2.2), DCDC_CONVERTER (11 pins), CAMERA (5 pins), CAN_PHY (C3.2 C4.2 R5.1 U1.2), EEPROM (C5.2 R3.1 U2.4)
VDD_SDCARD: HDConn_FEMALE (J1.72), SDcard (J7.4)
A0: TOP (J6.1), HDConn_FEMALE (J2.73)
A1: TOP (J6.2), HDConn_FEMALE (J2.75)
A2: TOP (J6.3), HDConn_FEMALE (J2.77)
A3: TOP (J6.4), HDConn_FEMALE (J2.79)
A4: TOP (J6.5), HDConn_FEMALE (J2.74)
A5: TOP (J6.6), HDConn_FEMALE (J2.76)
A6: TOP (J6.7), HDConn_FEMALE (J2.78)
A7: TOP (J6.8), HDConn_FEMALE (J2.80)
BOOT: TOP (BOOT_PUSHBUTTON.X PB1.1 R11.2), HDConn_FEMALE (J2.1 J2.48)
BT_SEL: TOP (BT_SEL.X SW2.1), HDConn_FEMALE (J2.3)
CAM.CK_N: HDConn_FEMALE (J2.20), CAMERA (J10.8)
CAM.CK_P: HDConn_FEMALE (J2.18), CAMERA (J10.9)
CAM.D0_N: HDConn_FEMALE (J2.16), CAMERA (J10.2)
CAM.D0_P: HDConn_FEMALE (J2.14), CAMERA (J10.3)
CAM.D1_N: HDConn_FEMALE (J2.12), CAMERA (J10.5)
CAM.D1_P: HDConn_FEMALE (J2.10), CAMERA (J10.6)
CAN1.RX: HDConn_FEMALE (J1.51), CAN_PHY (CANRX.X U1.4)
CAN1.TX: HDConn_FEMALE (J1.49), CAN_PHY (CANTX.X U1.1)
CD: HDConn_FEMALE (J1.67), SDcard (J7.CD1)
CLK: HDConn_FEMALE (J1.55), SDcard (J7.5)
CMD: HDConn_FEMALE (J1.57), SDcard (J7.3)
D0: HDConn_FEMALE (J1.59), SDcard (J7.7)
D1: HDConn_FEMALE (J1.61), SDcard (J7.8)
D2: HDConn_FEMALE (J1.63), SDcard (J7.1)
D3: HDConn_FEMALE (J1.65), SDcard (J7.2)
ETH_A_N: HDConn_FEMALE (J1.3), ETH_CONNECTOR (J8.10)
ETH_A_P: HDConn_FEMALE (J1.1), ETH_CONNECTOR (J8.9)
ETH_B_N: HDConn_FEMALE (J1.7), ETH_CONNECTOR (J8.8)
ETH_B_P: HDConn_FEMALE (J1.5), ETH_CONNECTOR (J8.7)
ETH_C_N: HDConn_FEMALE (J1.11), ETH_CONNECTOR (J8.6)
ETH_C_P: HDConn_FEMALE (J1.9), ETH_CONNECTOR (J8.5)
ETH_D_N: HDConn_FEMALE (J1.15), ETH_CONNECTOR (J8.4)
ETH_D_P: HDConn_FEMALE (J1.13), ETH_CONNECTOR (J8.3)
ETH_LED1: HDConn_FEMALE (J1.17), ETH_CONNECTOR (J8.14 R116.1)
ETH_LED2: HDConn_FEMALE (J1.19), ETH_CONNECTOR (R2.1 R96.2)
GPIO0: TOP (J6.12), HDConn_FEMALE (J2.46)
GPIO02_SDA: HDConn_FEMALE (J2.45), Headers (J5.3)
GPIO3: TOP (LED_USER.X R4.2), HDConn_FEMALE (J2.52)
GPIO03_SCL: HDConn_FEMALE (J2.47), Headers (J5.5)
GPIO4: HDConn_FEMALE (J2.54), CAN_PHY (CAN_EN.X R5.2 U1.8)
GPIO04_1WIRE: HDConn_FEMALE (J2.59), Headers (J5.7)
GPIO05: HDConn_FEMALE (J1.35), Headers (J5.29)
GPIO5: HDConn_FEMALE (J2.56), CAMERA (J10.11)
GPIO06: HDConn_FEMALE (J2.65), Headers (J5.31)
GPIO07_SPI0_CE1_N: HDConn_FEMALE (J2.63), Headers (J5.26)
GPIO08_SPI0_CE0_N: HDConn_FEMALE (J2.36), Headers (J5.24)
GPIO09_SPI0_MISO: HDConn_FEMALE (J2.40), Headers (J5.21)
GPIO10_SPI0_MOSI: HDConn_FEMALE (J2.42), Headers (J5.19)
GPIO11_SPI0_SCLK: HDConn_FEMALE (J2.38), Headers (J5.23)
GPIO12: HDConn_FEMALE (J1.33), Headers (J5.32)
GPIO13: HDConn_FEMALE (J2.67), Headers (J5.33)
GPIO14_TX: HDConn_FEMALE (J2.25), Headers (J5.8)
GPIO15_RX: HDConn_FEMALE (J2.27), Headers (J5.10)
GPIO16: HDConn_FEMALE (J2.60), Headers (J5.36)
GPIO17: HDConn_FEMALE (J2.50), Headers (J5.11)
GPIO18_PCM_CLK: HDConn_FEMALE (J1.56), Headers (J5.12)
GPIO19: HDConn_FEMALE (J1.58), Headers (J5.35)
GPIO20: HDConn_FEMALE (J1.60), Headers (J5.38)
GPIO21: HDConn_FEMALE (J1.62), Headers (J5.40)
GPIO22: HDConn_FEMALE (J2.53), Headers (J5.15)
GPIO23: HDConn_FEMALE (J2.49), Headers (J5.16)
GPIO24: HDConn_FEMALE (J2.51), Headers (J5.18)
GPIO25: HDConn_FEMALE (J2.61), Headers (J5.22)
GPIO26: HDConn_FEMALE (J2.62), Headers (J5.37)
GPIO27: HDConn_FEMALE (J2.58), Headers (J5.13)
I2C0.SCL: HDConn_FEMALE (J1.46), Headers (J5.28)
I2C0.SDA: HDConn_FEMALE (J1.44), Headers (J5.27)
I2C1.SCL: HDConn_FEMALE (J1.45), CAMERA (J10.13), EEPROM (EEPROM_SCL.X U2.6)
I2C1.SDA: HDConn_FEMALE (J1.43), CAMERA (J10.14), EEPROM (EEPROM_SDA.X U2.5)
JTAG_RST: TOP (J3.10), HDConn_FEMALE (J1.73)
JTAG_SCK: TOP (J3.4), HDConn_FEMALE (J1.77)
JTAG_SWD: TOP (J3.2), HDConn_FEMALE (J1.75)
JTAG_SWO: TOP (J3.6), HDConn_FEMALE (J1.79)
JTAG_TDI: TOP (J3.8), HDConn_FEMALE (J1.78)
JTAG_TRST: TOP (J3.9), HDConn_FEMALE (J1.80)
LICELL: TOP (J6.11), HDConn_FEMALE (J2.7)
NetCENTER_TAP_X: TOP (CENTER_TAP.X SW2.2), ETH_CONNECTOR (J8.2)
NetD2_A: TOP (J9.1), DCDC_CONVERTER (D2.A)
NetJ9_5: TOP (J9.5), CAN_PHY (U1.7)
NetJ9_6: TOP (J9.6), CAN_PHY (U1.6)
PWM.7: TOP (J6.9), HDConn_FEMALE (J2.64)
PWM.8: TOP (J6.10), HDConn_FEMALE (J2.66)
PWM.9: TOP (J11.1), HDConn_FEMALE (J2.68)
SERIAL2.RX: TOP (J6.16), HDConn_FEMALE (J2.28)
SERIAL2.TX: TOP (J6.14), HDConn_FEMALE (J2.26)
USB0_D_N: HDConn_FEMALE (J1.28), USB (D1.3 J4.2)
USB0_D_P: HDConn_FEMALE (J1.26), USB (D1.2 J4.3)

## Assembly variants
ASX00049: not fitted R7 R8 R9 R10 R35 R36 SW1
